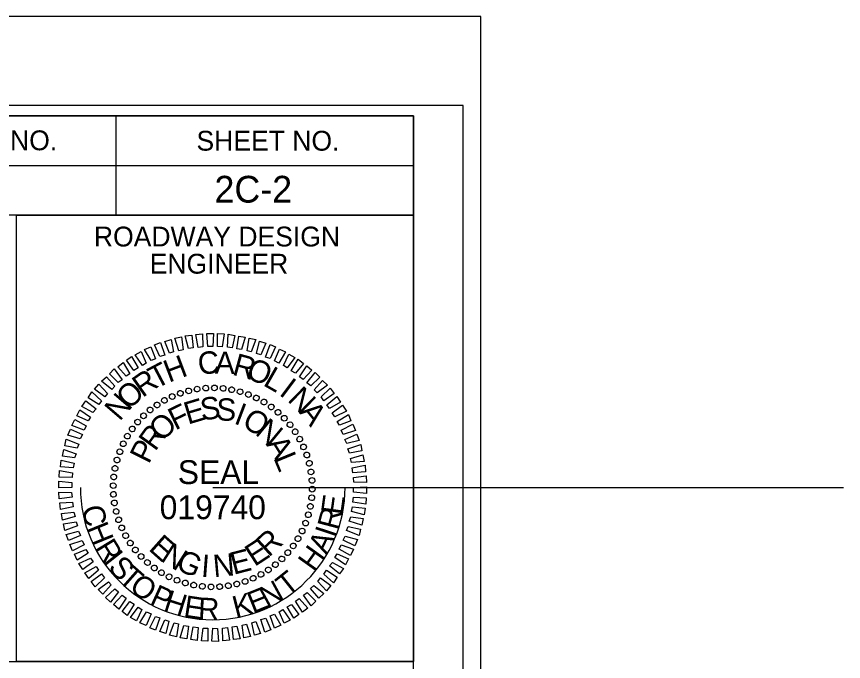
# Model space of a CAD drawing. Extents: x 1252282 to 1252460, y 733735 to 733845.
# Drawn here: x 1252438.88 to 1252459.72, y 733828.25 to 733844.5 of the extents above; entities that cross this region are included whole.
import ezdxf

# ---------------------------------------------------------------- set-up
doc = ezdxf.new("R2010")
doc.units = 0
for name, color, linetype in [('Scratch_Level_0', 7, 'Continuous'), ('Scratch_Level_1', 7, 'Continuous'), ('Sheet Cutting Line CELL', 7, 'Continuous'), ('Sheet Data Field CELL', 7, 'Continuous'), ('Sheet Plot Border Inside CELL', 7, 'Continuous'), ('Sheet Plot Border Outside CELL', 7, 'Continuous'), ('Sheet Professional Seal CELL', 7, 'Continuous'), ('Sheet Sticker Exception Certification CELL', 7, 'Continuous'), ('Sheet Typical CELL', 7, 'Continuous')]:
    doc.layers.add(name, color=color, linetype=linetype)

msp = doc.modelspace()

# ---------------------------------------------------------------- linework, layer by layer
at = {"layer": 'Scratch_Level_0'}
msp.add_arc((1252443.822, 733832.634), 3.336, 180, 360, dxfattribs=at)
at = {"layer": 'Scratch_Level_1'}
for q in [(1252459.72, 733832.634), (1252443.822, 733832.634)]:
    msp.add_line((1252443.822, 733832.634), q, dxfattribs=at)
at = {"layer": 'Sheet Cutting Line CELL'}
msp.add_line((1252450.583, 733844.502), (1252282.183, 733844.502), dxfattribs=at)
at = {"layer": 'Sheet Plot Border Inside CELL'}
msp.add_lwpolyline([(1252450.133, 733842.257), (1252283.483, 733842.257), (1252283.483, 733736.747), (1252450.133, 733736.747)], close=True, dxfattribs=at)
at = {"layer": 'Sheet Plot Border Outside CELL'}
msp.add_lwpolyline([(1252450.583, 733844.502), (1252282.183, 733844.502), (1252282.183, 733734.502), (1252450.583, 733734.502)], close=True, dxfattribs=at)
at = {"layer": 'Sheet Professional Seal CELL'}
for p, q in [((1252443.002, 733835.009), (1252443.002, 733835.009)), ((1252443.212, 733835.069), (1252443.212, 733835.069)), ((1252443.432, 733835.109), (1252443.432, 733835.109)), ((1252443.647, 733835.139), (1252443.647, 733835.139)), ((1252443.867, 733835.144), (1252443.867, 733835.144)), ((1252444.087, 733835.129), (1252444.087, 733835.129)), ((1252444.302, 733835.094), (1252444.302, 733835.094)), ((1252444.512, 733835.049), (1252444.512, 733835.049)), ((1252442.607, 733834.829), (1252442.607, 733834.829)), ((1252442.802, 733834.929), (1252442.802, 733834.929)), ((1252444.722, 733834.979), (1252444.722, 733834.979)), ((1252444.922, 733834.889), (1252444.922, 733834.889)), ((1252442.242, 733834.589), (1252442.242, 733834.589)), ((1252442.417, 733834.714), (1252442.417, 733834.714)), ((1252445.117, 733834.789), (1252445.117, 733834.789)), ((1252445.297, 733834.664), (1252445.297, 733834.664)), ((1252442.077, 733834.439), (1252442.077, 733834.439)), ((1252445.472, 733834.529), (1252445.472, 733834.529)), ((1252441.927, 733834.284), (1252441.927, 733834.284)), ((1252445.627, 733834.379), (1252445.627, 733834.379)), ((1252445.777, 733834.214), (1252445.777, 733834.214)), ((1252441.792, 733834.109), (1252441.792, 733834.109)), ((1252445.902, 733834.039), (1252445.902, 733834.039)), ((1252441.667, 733833.929), (1252441.667, 733833.929)), ((1252446.017, 733833.849), (1252446.017, 733833.849)), ((1252441.567, 733833.734), (1252441.567, 733833.734)), ((1252446.117, 733833.654), (1252446.117, 733833.654)), ((1252441.477, 733833.534), (1252441.477, 733833.534)), ((1252446.197, 733833.454), (1252446.197, 733833.454)), ((1252441.407, 733833.324), (1252441.407, 733833.324)), ((1252446.257, 733833.244), (1252446.257, 733833.244)), ((1252441.362, 733833.114), (1252441.362, 733833.114)), ((1252446.297, 733833.024), (1252446.297, 733833.024)), ((1252441.327, 733832.899), (1252441.327, 733832.899)), ((1252446.327, 733832.809), (1252446.327, 733832.809)), ((1252441.312, 733832.679), (1252441.312, 733832.679)), ((1252443.822, 733832.634), (1252443.822, 733832.634)), ((1252446.332, 733832.589), (1252446.332, 733832.589)), ((1252441.317, 733832.459), (1252441.317, 733832.459)), ((1252446.317, 733832.369), (1252446.317, 733832.369)), ((1252441.347, 733832.244), (1252441.347, 733832.244)), ((1252446.282, 733832.154), (1252446.282, 733832.154)), ((1252441.387, 733832.024), (1252441.387, 733832.024)), ((1252446.237, 733831.944), (1252446.237, 733831.944)), ((1252441.447, 733831.814), (1252441.447, 733831.814)), ((1252446.167, 733831.734), (1252446.167, 733831.734)), ((1252441.527, 733831.614), (1252441.527, 733831.614)), ((1252446.077, 733831.534), (1252446.077, 733831.534)), ((1252441.627, 733831.419), (1252441.627, 733831.419)), ((1252445.977, 733831.339), (1252445.977, 733831.339)), ((1252441.742, 733831.229), (1252441.742, 733831.229)), ((1252441.867, 733831.054), (1252441.867, 733831.054)), ((1252445.852, 733831.159), (1252445.852, 733831.159)), ((1252442.017, 733830.889), (1252442.017, 733830.889)), ((1252445.717, 733830.984), (1252445.717, 733830.984)), ((1252442.172, 733830.739), (1252442.172, 733830.739)), ((1252445.402, 733830.679), (1252445.402, 733830.679)), ((1252445.567, 733830.829), (1252445.567, 733830.829)), ((1252442.347, 733830.604), (1252442.347, 733830.604)), ((1252442.527, 733830.479), (1252442.527, 733830.479)), ((1252445.037, 733830.439), (1252445.037, 733830.439)), ((1252445.227, 733830.554), (1252445.227, 733830.554)), ((1252442.722, 733830.379), (1252442.722, 733830.379)), ((1252442.922, 733830.289), (1252442.922, 733830.289)), ((1252443.132, 733830.219), (1252443.132, 733830.219)), ((1252444.642, 733830.259), (1252444.642, 733830.259)), ((1252444.842, 733830.339), (1252444.842, 733830.339)), ((1252443.342, 733830.174), (1252443.342, 733830.174)), ((1252443.557, 733830.139), (1252443.557, 733830.139)), ((1252443.777, 733830.124), (1252443.777, 733830.124)), ((1252443.997, 733830.129), (1252443.997, 733830.129)), ((1252444.212, 733830.159), (1252444.212, 733830.159)), ((1252444.432, 733830.199), (1252444.432, 733830.199))]:
    msp.add_line(p, q, dxfattribs=at)
for points in [[(1252443.212, 733836.134), (1252443.132, 733836.454), (1252443.297, 733836.469), (1252443.332, 733836.149)], [(1252443.452, 733836.164), (1252443.397, 733836.484), (1252443.567, 733836.504), (1252443.572, 733836.179)], [(1252443.702, 733836.189), (1252443.677, 733836.514), (1252443.842, 733836.509), (1252443.822, 733836.184)], [(1252443.942, 733836.184), (1252443.942, 733836.509), (1252444.107, 733836.504), (1252444.062, 733836.179)], [(1252444.192, 733836.169), (1252444.212, 733836.494), (1252444.377, 733836.464), (1252444.312, 733836.149)], [(1252442.487, 733835.934), (1252442.357, 733836.224), (1252442.507, 733836.284), (1252442.612, 733835.964)], [(1252442.732, 733836.014), (1252442.617, 733836.314), (1252442.772, 733836.359), (1252442.837, 733836.049)], [(1252442.972, 733836.079), (1252442.867, 733836.394), (1252443.037, 733836.429), (1252443.077, 733836.104)], [(1252444.432, 733836.129), (1252444.477, 733836.449), (1252444.642, 733836.424), (1252444.552, 733836.114)], [(1252444.687, 733836.074), (1252444.737, 733836.399), (1252444.907, 733836.359), (1252444.792, 733836.049)], [(1252444.927, 733836.009), (1252445.002, 733836.319), (1252445.157, 733836.269), (1252445.032, 733835.974)], [(1252442.052, 733835.709), (1252441.867, 733835.979), (1252442.022, 733836.059), (1252442.147, 733835.769)], [(1252442.267, 733835.829), (1252442.107, 733836.109), (1252442.262, 733836.179), (1252442.377, 733835.874)], [(1252445.152, 733835.919), (1252445.267, 733836.234), (1252445.407, 733836.174), (1252445.267, 733835.884)], [(1252445.377, 733835.824), (1252445.502, 733836.119), (1252445.657, 733836.049), (1252445.487, 733835.769)], [(1252441.832, 733835.584), (1252441.647, 733835.839), (1252441.777, 733835.934), (1252441.942, 733835.644)], [(1252445.607, 733835.709), (1252445.742, 733835.994), (1252445.892, 733835.909), (1252445.702, 733835.649)], [(1252445.802, 733835.574), (1252445.977, 733835.864), (1252446.107, 733835.759), (1252445.912, 733835.514)], [(1252441.642, 733835.434), (1252441.427, 733835.674), (1252441.562, 733835.779), (1252441.737, 733835.499)], [(1252446.007, 733835.424), (1252446.192, 733835.699), (1252446.322, 733835.589), (1252446.102, 733835.354)], [(1252441.277, 733835.104), (1252441.022, 733835.309), (1252441.147, 733835.424), (1252441.357, 733835.184)], [(1252441.442, 733835.279), (1252441.222, 733835.499), (1252441.342, 733835.619), (1252441.537, 733835.349)], [(1252446.197, 733835.269), (1252446.402, 733835.529), (1252446.522, 733835.409), (1252446.292, 733835.194)], [(1252441.102, 733834.914), (1252440.842, 733835.109), (1252440.952, 733835.239), (1252441.172, 733835.004)], [(1252446.377, 733835.094), (1252446.592, 733835.329), (1252446.712, 733835.209), (1252446.452, 733835.014)], [(1252440.952, 733834.724), (1252440.682, 733834.894), (1252440.777, 733835.039), (1252441.017, 733834.819)], [(1252446.552, 733834.914), (1252446.782, 733835.139), (1252446.887, 733835.004), (1252446.622, 733834.814)], [(1252440.802, 733834.524), (1252440.522, 733834.674), (1252440.622, 733834.814), (1252440.882, 733834.614)], [(1252446.702, 733834.719), (1252446.947, 733834.929), (1252447.042, 733834.784), (1252446.762, 733834.624)], [(1252440.682, 733834.309), (1252440.397, 733834.434), (1252440.472, 733834.589), (1252440.742, 733834.404)], [(1252446.832, 733834.514), (1252447.097, 733834.704), (1252447.192, 733834.554), (1252446.902, 733834.414)], [(1252446.962, 733834.294), (1252447.242, 733834.469), (1252447.307, 733834.314), (1252447.022, 733834.199)], [(1252440.582, 733834.079), (1252440.272, 733834.194), (1252440.347, 733834.349), (1252440.632, 733834.189)], [(1252447.062, 733834.079), (1252447.357, 733834.229), (1252447.422, 733834.069), (1252447.112, 733833.969)], [(1252440.482, 733833.859), (1252440.172, 733833.949), (1252440.237, 733834.104), (1252440.537, 733833.964)], [(1252447.152, 733833.844), (1252447.457, 733833.974), (1252447.512, 733833.819), (1252447.202, 733833.739)], [(1252440.407, 733833.619), (1252440.097, 733833.684), (1252440.132, 733833.849), (1252440.447, 733833.724)], [(1252440.342, 733833.379), (1252440.032, 733833.419), (1252440.067, 733833.589), (1252440.382, 733833.484)], [(1252447.232, 733833.604), (1252447.552, 733833.719), (1252447.582, 733833.554), (1252447.267, 733833.499)], [(1252447.292, 733833.364), (1252447.607, 733833.459), (1252447.637, 733833.289), (1252447.322, 733833.259)], [(1252440.302, 733833.124), (1252439.982, 733833.154), (1252440.002, 733833.324), (1252440.327, 733833.244)], [(1252447.337, 733833.124), (1252447.662, 733833.194), (1252447.677, 733833.024), (1252447.357, 733833.004)], [(1252440.277, 733832.884), (1252439.952, 733832.894), (1252439.962, 733833.059), (1252440.287, 733833.004)], [(1252447.367, 733832.884), (1252447.692, 733832.924), (1252447.702, 733832.754), (1252447.377, 733832.764)], [(1252440.272, 733832.634), (1252439.947, 733832.619), (1252439.947, 733832.789), (1252440.272, 733832.754)], [(1252440.277, 733832.384), (1252439.952, 733832.344), (1252439.942, 733832.514), (1252440.267, 733832.504)], [(1252447.372, 733832.634), (1252447.697, 733832.649), (1252447.697, 733832.479), (1252447.372, 733832.514)], [(1252447.367, 733832.384), (1252447.692, 733832.374), (1252447.682, 733832.209), (1252447.357, 733832.264)], [(1252440.307, 733832.144), (1252439.982, 733832.074), (1252439.967, 733832.244), (1252440.287, 733832.264)], [(1252447.342, 733832.144), (1252447.662, 733832.114), (1252447.642, 733831.944), (1252447.317, 733832.024)], [(1252440.352, 733831.904), (1252440.037, 733831.809), (1252440.007, 733831.979), (1252440.322, 733832.009)], [(1252447.302, 733831.889), (1252447.612, 733831.849), (1252447.577, 733831.679), (1252447.262, 733831.784)], [(1252440.412, 733831.664), (1252440.092, 733831.549), (1252440.062, 733831.714), (1252440.377, 733831.769)], [(1252440.492, 733831.424), (1252440.187, 733831.294), (1252440.132, 733831.449), (1252440.442, 733831.529)], [(1252447.237, 733831.649), (1252447.547, 733831.584), (1252447.512, 733831.419), (1252447.197, 733831.544)], [(1252440.582, 733831.189), (1252440.287, 733831.039), (1252440.222, 733831.199), (1252440.532, 733831.299)], [(1252447.162, 733831.409), (1252447.472, 733831.319), (1252447.407, 733831.164), (1252447.107, 733831.304)], [(1252440.682, 733830.974), (1252440.402, 733830.799), (1252440.337, 733830.954), (1252440.622, 733831.069)], [(1252447.062, 733831.189), (1252447.372, 733831.074), (1252447.297, 733830.919), (1252447.012, 733831.079)], [(1252440.812, 733830.754), (1252440.547, 733830.564), (1252440.452, 733830.714), (1252440.742, 733830.854)], [(1252446.962, 733830.959), (1252447.247, 733830.834), (1252447.172, 733830.679), (1252446.902, 733830.864)], [(1252440.942, 733830.549), (1252440.697, 733830.339), (1252440.602, 733830.484), (1252440.882, 733830.644)], [(1252446.842, 733830.744), (1252447.122, 733830.594), (1252447.022, 733830.454), (1252446.762, 733830.654)], [(1252441.092, 733830.354), (1252440.862, 733830.129), (1252440.757, 733830.264), (1252441.022, 733830.454)], [(1252446.692, 733830.544), (1252446.962, 733830.374), (1252446.867, 733830.229), (1252446.627, 733830.449)], [(1252441.267, 733830.174), (1252441.052, 733829.939), (1252440.932, 733830.059), (1252441.192, 733830.254)], [(1252446.542, 733830.354), (1252446.802, 733830.159), (1252446.692, 733830.029), (1252446.472, 733830.264)], [(1252441.447, 733829.999), (1252441.242, 733829.739), (1252441.122, 733829.859), (1252441.352, 733830.074)], [(1252446.367, 733830.164), (1252446.622, 733829.959), (1252446.497, 733829.844), (1252446.287, 733830.084)], [(1252441.637, 733829.844), (1252441.452, 733829.569), (1252441.322, 733829.679), (1252441.542, 733829.914)], [(1252446.002, 733829.834), (1252446.217, 733829.594), (1252446.082, 733829.489), (1252445.907, 733829.769)], [(1252446.202, 733829.989), (1252446.422, 733829.769), (1252446.302, 733829.649), (1252446.107, 733829.919)], [(1252441.842, 733829.694), (1252441.667, 733829.404), (1252441.537, 733829.509), (1252441.732, 733829.754)], [(1252442.037, 733829.559), (1252441.902, 733829.274), (1252441.752, 733829.359), (1252441.942, 733829.619)], [(1252445.812, 733829.684), (1252445.997, 733829.429), (1252445.867, 733829.334), (1252445.702, 733829.624)], [(1252442.267, 733829.444), (1252442.142, 733829.149), (1252441.987, 733829.219), (1252442.157, 733829.499)], [(1252442.492, 733829.349), (1252442.377, 733829.034), (1252442.237, 733829.094), (1252442.377, 733829.384)], [(1252445.377, 733829.439), (1252445.537, 733829.159), (1252445.382, 733829.089), (1252445.267, 733829.394)], [(1252445.592, 733829.559), (1252445.777, 733829.289), (1252445.622, 733829.209), (1252445.497, 733829.499)], [(1252442.717, 733829.259), (1252442.642, 733828.949), (1252442.487, 733828.999), (1252442.612, 733829.294)], [(1252442.957, 733829.194), (1252442.907, 733828.869), (1252442.737, 733828.909), (1252442.852, 733829.219)], [(1252444.672, 733829.189), (1252444.777, 733828.874), (1252444.607, 733828.839), (1252444.567, 733829.164)], [(1252444.912, 733829.254), (1252445.027, 733828.954), (1252444.872, 733828.909), (1252444.807, 733829.219)], [(1252445.157, 733829.334), (1252445.287, 733829.044), (1252445.137, 733828.984), (1252445.032, 733829.304)], [(1252443.212, 733829.139), (1252443.167, 733828.819), (1252443.002, 733828.844), (1252443.092, 733829.154)], [(1252443.452, 733829.099), (1252443.432, 733828.774), (1252443.267, 733828.804), (1252443.332, 733829.119)], [(1252443.702, 733829.084), (1252443.702, 733828.759), (1252443.537, 733828.764), (1252443.582, 733829.089)], [(1252443.942, 733829.079), (1252443.967, 733828.754), (1252443.802, 733828.759), (1252443.822, 733829.084)], [(1252444.192, 733829.104), (1252444.247, 733828.784), (1252444.077, 733828.764), (1252444.072, 733829.089)], [(1252444.432, 733829.134), (1252444.512, 733828.814), (1252444.347, 733828.799), (1252444.312, 733829.119)]]:
    msp.add_lwpolyline(points, close=True, dxfattribs=at)
for centre, major_axis in [((1252443.866, 733835.142), (0.0013, 0.072)), ((1252442.802, 733834.925), (-0.0293, 0.0658)), ((1252443.006, 733835.005), (-0.0234, 0.0681)), ((1252443.216, 733835.067), (-0.0174, 0.0699)), ((1252443.43, 733835.111), (-0.0113, 0.0711)), ((1252443.647, 733835.136), (-0.005, 0.0718)), ((1252444.084, 733835.128), (0.0075, 0.0716)), ((1252444.301, 733835.096), (0.0137, 0.0707)), ((1252444.514, 733835.045), (0.0198, 0.0692)), ((1252444.721, 733834.975), (0.0258, 0.0672)), ((1252442.606, 733834.827), (-0.0349, 0.063)), ((1252444.922, 733834.888), (0.0316, 0.0647)), ((1252445.114, 733834.784), (0.0371, 0.0617)), ((1252442.244, 733834.583), (-0.0453, 0.056)), ((1252442.42, 733834.713), (-0.0403, 0.0597)), ((1252445.296, 733834.663), (0.0423, 0.0582)), ((1252445.468, 733834.527), (0.0472, 0.0543)), ((1252442.08, 733834.438), (-0.05, 0.0518)), ((1252445.626, 733834.376), (0.0518, 0.05)), ((1252441.793, 733834.108), (-0.0582, 0.0423)), ((1252441.929, 733834.279), (-0.0543, 0.0472)), ((1252445.771, 733834.212), (0.056, 0.0453)), ((1252441.672, 733833.926), (-0.0617, 0.0371)), ((1252445.901, 733834.036), (0.0597, 0.0403)), ((1252441.568, 733833.733), (-0.0647, 0.0316)), ((1252446.016, 733833.85), (0.063, 0.0349)), ((1252441.481, 733833.533), (-0.0672, 0.0258)), ((1252446.113, 733833.654), (0.0658, 0.0293)), ((1252441.411, 733833.325), (-0.0692, 0.0198)), ((1252446.194, 733833.45), (0.0681, 0.0234)), ((1252441.36, 733833.112), (-0.0707, 0.0137)), ((1252446.256, 733833.241), (0.0699, 0.0174)), ((1252441.328, 733832.896), (-0.0716, 0.0075)), ((1252446.299, 733833.026), (0.0711, 0.0113)), ((1252441.315, 733832.678), (-0.072, 0.0013)), ((1252446.324, 733832.809), (0.0718, 0.005)), ((1252441.32, 733832.459), (-0.0718, -0.005)), ((1252446.33, 733832.59), (0.072, -0.0013)), ((1252441.345, 733832.242), (-0.0711, -0.0113)), ((1252446.317, 733832.372), (0.0716, -0.0075)), ((1252441.389, 733832.027), (-0.0699, -0.0174)), ((1252446.284, 733832.155), (0.0707, -0.0137)), ((1252441.451, 733831.817), (-0.0681, -0.0234)), ((1252446.233, 733831.943), (0.0692, -0.0198)), ((1252441.531, 733831.614), (-0.0658, -0.0293)), ((1252446.164, 733831.735), (0.0672, -0.0258)), ((1252441.629, 733831.418), (-0.063, -0.0349)), ((1252446.076, 733831.534), (0.0647, -0.0316)), ((1252441.743, 733831.231), (-0.0597, -0.0403)), ((1252445.972, 733831.342), (0.0617, -0.0371)), ((1252441.873, 733831.056), (-0.056, -0.0453)), ((1252445.715, 733830.989), (0.0543, -0.0472)), ((1252445.851, 733831.16), (0.0582, -0.0423)), ((1252442.018, 733830.892), (-0.0518, -0.05)), ((1252445.564, 733830.83), (0.05, -0.0518)), ((1252442.177, 733830.741), (-0.0472, -0.0543)), ((1252442.348, 733830.605), (-0.0423, -0.0582)), ((1252445.225, 733830.555), (0.0403, -0.0597)), ((1252445.401, 733830.685), (0.0453, -0.056)), ((1252442.531, 733830.484), (-0.0371, -0.0617)), ((1252442.723, 733830.38), (-0.0316, -0.0647)), ((1252444.842, 733830.343), (0.0293, -0.0658)), ((1252445.038, 733830.44), (0.0349, -0.063)), ((1252442.923, 733830.293), (-0.0258, -0.0672)), ((1252443.131, 733830.223), (-0.0198, -0.0692)), ((1252443.344, 733830.172), (-0.0137, -0.0707)), ((1252443.56, 733830.14), (-0.0075, -0.0716)), ((1252444.215, 733830.157), (0.0113, -0.0711)), ((1252444.429, 733830.2), (0.0174, -0.0699)), ((1252444.639, 733830.263), (0.0234, -0.0681)), ((1252443.779, 733830.126), (-0.0013, -0.072)), ((1252443.997, 733830.132), (0.005, -0.0718))]:
    msp.add_ellipse(centre, major_axis=major_axis, ratio=0.999708, dxfattribs=at)
at = {"layer": 'Sheet Sticker Exception Certification CELL'}
msp.add_line((1252428.878, 733828.247), (1252448.882, 733828.247), dxfattribs=at)
at = {"layer": 'Sheet Typical CELL'}
for p, q in [((1252441.383, 733841.997), (1252441.383, 733839.497)), ((1252428.878, 733840.747), (1252448.883, 733840.747)), ((1252448.883, 733839.497), (1252448.883, 733828.252))]:
    msp.add_line(p, q, dxfattribs=at)
for points in [[(1252448.883, 733842.002), (1252298.883, 733842.002), (1252298.883, 733737.002), (1252448.883, 733737.002)], [(1252428.878, 733842.002), (1252448.883, 733842.002), (1252448.883, 733839.497), (1252428.878, 733839.497)], [(1252438.878, 733839.497), (1252448.883, 733839.497), (1252448.883, 733828.247), (1252438.878, 733828.247)]]:
    msp.add_lwpolyline(points, close=True, dxfattribs=at)

# ---------------------------------------------------------------- texts
at = {"layer": 'Sheet Data Field CELL'}
msp.add_text('2C-2', height=0.675, dxfattribs=at).set_placement((1252443.867, 733839.812))
at = {"layer": 'Sheet Professional Seal CELL'}
for s, height, rotation, p in [('C', 0.564, 6.2199, (1252443.477, 733835.469)), ('A', 0.564, 359.0203, (1252443.872, 733835.499)), ('H', 0.564, 20.6195, (1252442.717, 733835.269)), ('R', 0.564, 344.6211, (1252444.292, 733835.479)), ('O', 0.564, 337.4212, (1252444.627, 733835.404)), ('T', 0.564, 27.8198, (1252442.392, 733835.104)), ('L', 0.564, 330.2209, (1252445.067, 733835.219)), ('R', 0.564, 35.0205, (1252442.052, 733834.884)), ('O', 0.564, 42.2217, (1252441.707, 733834.574)), ('I', 0.564, 323.0201, (1252445.472, 733834.979)), ('N', 0.564, 49.4235, (1252441.477, 733834.284)), ('N', 0.564, 315.8189, (1252445.687, 733834.824)), ('E', 0.564, 16.6111, (1252443.197, 733834.214)), ('S', 0.564, 7.2556, (1252443.542, 733834.319)), ('S', 0.564, 357.9004, (1252443.902, 733834.324)), ('F', 0.564, 25.967, (1252442.877, 733834.064)), ('I', 0.564, 339.1896, (1252444.332, 733834.254)), ('O', 0.564, 329.8335, (1252444.532, 733834.184)), ('A', 0.564, 308.6172, (1252445.982, 733834.529)), ('O', 0.564, 44.6812, (1252442.547, 733833.769)), ('N', 0.564, 320.4766, (1252444.867, 733833.984)), ('R', 0.564, 54.0397, (1252442.372, 733833.524)), ('P', 0.564, 63.3989, (1252442.212, 733833.204)), ('A', 0.564, 301.7603, (1252445.152, 733833.724)), ('L', 0.564, 292.4008, (1252445.347, 733833.379)), ('SEAL', 0.5998, 360, (1252442.942, 733832.719)), ('019740', 0.5998, 360, (1252442.486, 733831.833)), ('E', 0.55, 82.1825, (1252447.093, 733831.924)), ('C', 0.55, 283.2464, (1252440.515, 733832.121)), ('R', 0.55, 75.2561, (1252446.983, 733831.535)), ('H', 0.55, 292.1191, (1252440.634, 733831.617)), ('R', 0.564, 42.4814, (1252445.232, 733830.859)), ('I', 0.55, 71.7356, (1252446.91, 733831.343)), ('R', 0.55, 301.3639, (1252440.839, 733831.118)), ('E', 0.564, 318.2769, (1252442.182, 733831.069)), ('E', 0.564, 33.1241, (1252444.877, 733830.624)), ('A', 0.55, 63.5498, (1252446.694, 733830.917)), ('I', 0.55, 308.2904, (1252441.044, 733830.769)), ('N', 0.564, 327.634, (1252442.482, 733830.799)), ('E', 0.564, 14.4118, (1252444.347, 733830.429)), ('H', 0.55, 54.305, (1252446.381, 733830.477)), ('S', 0.55, 311.8108, (1252441.163, 733830.602)), ('G', 0.564, 336.9902, (1252442.862, 733830.574)), ('I', 0.564, 355.7012, (1252443.517, 733830.384)), ('N', 0.564, 5.0564, (1252443.852, 733830.369)), ('T', 0.55, 318.5942, (1252441.422, 733830.302)), ('T', 0.55, 38.5631, (1252445.7, 733829.864)), ('O', 0.55, 324.8909, (1252441.692, 733830.053)), ('N', 0.55, 28.6314, (1252445.194, 733829.582)), ('P', 0.55, 335.5954, (1252442.209, 733829.702)), ('H', 0.55, 342.1784, (1252442.555, 733829.537)), ('E', 0.55, 22.0484, (1252444.835, 733829.445)), ('E', 0.55, 351.4232, (1252443.069, 733829.373)), ('R', 0.55, 358.0062, (1252443.448, 733829.309)), ('K', 0.55, 14.3778, (1252444.401, 733829.338))]:
    msp.add_text(s, height=height, rotation=rotation, dxfattribs=at).set_placement(p)
at = {"layer": 'Sheet Typical CELL'}
for s, height, p in [('PROJECT REFERENCE NO.', 0.50001, (1252431.098, 733841.132)), ('SHEET NO.', 0.5, (1252443.413, 733841.122)), ('ROADWAY DESIGN', 0.50001, (1252440.828, 733838.707)), ('ENGINEER', 0.5, (1252442.233, 733838.022))]:
    msp.add_text(s, height=height, dxfattribs=at).set_placement(p)

doc.saveas('drawing.dxf')
